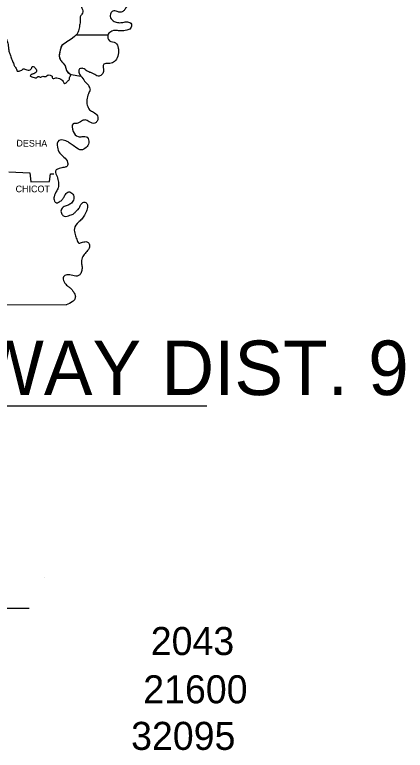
# Model space of a CAD drawing. Extents: x 309389.3 to 309420.2, y 336441.4 to 336461.2.
# Drawn here: x 309417.747 to 309420.196, y 336451.782 to 336456.398 of the extents above; entities that cross this region are included whole.
import ezdxf

# ---------------------------------------------------------------- set-up
doc = ezdxf.new("R2010")
doc.units = 0
doc.layers.add('Level 1', color=7, linetype='Continuous')
doc.layers.add('Level 63', color=7, linetype='Continuous')

msp = doc.modelspace()

# ---------------------------------------------------------------- linework, layer by layer
at = {"layer": 'Level 63'}
for p, q in [((309418.3313, 336456.2694), (309418.1305, 336456.2694)), ((309413.7435, 336453.9437), (309418.9521, 336453.9437)), ((309417.9364, 336452.8683), (309417.9364, 336452.8683)), ((309414.7103, 336452.6728), (309417.8386, 336452.6728))]:
    msp.add_line(p, q, dxfattribs=at)
for points in [[(309418.1289, 336456.2674), (309418.1221, 336456.2615), (309418.1016, 336456.2449), (309418.084, 336456.2352), (309418.0654, 336456.2215), (309418.0429, 336456.2048), (309418.0322, 336456.1765), (309418.0263, 336456.1374), (309418.0341, 336456.1139), (309418.0517, 336456.0934), (309418.0634, 336456.0768), (309418.0722, 336456.0475), (309418.0938, 336456.0269), (309418.1006, 336456.024), (309418.1622, 336456.0132)], [(309414.4855, 336455.3749), (309414.4874, 336454.584), (309418.0703, 336454.5781)], [(309417.7105, 336455.413), (309417.8415, 336455.4052), (309417.8474, 336455.3485), (309417.9657, 336455.3524), (309417.9706, 336455.4003), (309417.9931, 336455.4003)]]:
    msp.add_lwpolyline(points, dxfattribs=at)
for points in [[(309418.8934, 336457.2186), (309418.8709, 336457.1903), (309418.8377, 336457.2079), (309418.8377, 336457.2313), (309418.8426, 336457.2558), (309418.8309, 336457.2714), (309418.8103, 336457.2646), (309418.8103, 336457.2343), (309418.8084, 336457.2049), (309418.8025, 336457.1629), (309418.8162, 336457.1502), (309418.8475, 336457.1463), (309418.87, 336457.1404), (309418.8836, 336457.1179), (309418.8827, 336457.0905), (309418.8719, 336457.0642), (309418.8563, 336457.0426), (309418.8318, 336457.0348), (309418.8123, 336457.0475), (309418.8045, 336457.0729), (309418.7957, 336457.0954), (309418.779, 336457.1121), (309418.7614, 336457.0935), (309418.7575, 336457.0593), (309418.7585, 336457.0299), (309418.7585, 336456.9899), (309418.7839, 336456.9635), (309418.7996, 336456.9332), (309418.7947, 336456.9058), (309418.7761, 336456.8735), (309418.7683, 336456.8452), (309418.7605, 336456.807), (309418.7614, 336456.765), (309418.7546, 336456.7239), (309418.7409, 336456.6966), (309418.7155, 336456.6741), (309418.6989, 336456.6594), (309418.6852, 336456.6448), (309418.6784, 336456.6154), (309418.6735, 336456.5949), (309418.6549, 336456.5705), (309418.6402, 336456.5685), (309418.6285, 336456.5783), (309418.6246, 336456.5949), (309418.6246, 336456.6115), (309418.6168, 336456.6281), (309418.5923, 336456.635), (309418.5728, 336456.634), (309418.564, 336456.6203), (309418.5767, 336456.5822), (309418.5816, 336456.5578), (309418.5747, 336456.5245), (309418.5786, 336456.5206), (309418.5434, 336456.502), (309418.5151, 336456.4991), (309418.4916, 336456.4923), (309418.4691, 336456.4776), (309418.4584, 336456.4561), (309418.4428, 336456.4385), (309418.4291, 336456.4219), (309418.4105, 336456.4141), (309418.39, 336456.418), (309418.3626, 336456.4209), (309418.3469, 336456.4013), (309418.3518, 336456.373), (309418.3704, 336456.3564), (309418.3978, 336456.3486), (309418.4261, 336456.3505), (309418.4535, 336456.3534), (309418.4789, 336456.3398), (309418.474, 336456.3134), (309418.4496, 336456.3007), (309418.4134, 336456.2967), (309418.3841, 336456.2997), (309418.3489, 336456.2919), (309418.3313, 336456.2694), (309418.3411, 336456.2352), (309418.3792, 336456.2215), (309418.3968, 336456.1892), (309418.3978, 336456.1589), (309418.3851, 336456.1188), (309418.3675, 336456.1002), (309418.3333, 336456.0924), (309418.3069, 336456.0875), (309418.303, 336456.0426), (309418.2912, 336456.0201), (309418.2707, 336456.0132), (309418.2414, 336456.0279), (309418.2238, 336456.0347), (309418.2023, 336456.0445), (309418.1749, 336456.0611), (309418.1544, 336456.0582), (309418.1602, 336456.0152), (309418.1622, 336456.0132), (309418.1856, 336455.981), (309418.2091, 336455.9556), (309418.2199, 336455.9253)], [(309417.8806, 336456.9038), (309417.8836, 336456.8637), (309417.907, 336456.8579), (309417.9168, 336456.8471), (309417.9217, 336456.8246), (309417.9383, 336456.8149), (309417.9608, 336456.8012), (309417.9745, 336456.7914), (309417.9843, 336456.7758), (309417.9901, 336456.7503), (309418.0058, 336456.7337), (309418.0273, 336456.7259), (309418.0429, 336456.7073), (309418.0527, 336456.6809), (309418.0683, 336456.6692), (309418.084, 336456.6487), (309418.0918, 336456.6399), (309418.1055, 336456.6164), (309418.1192, 336456.6047), (309418.1289, 336456.5978), (309418.1446, 336456.593), (309418.1641, 336456.5802), (309418.1768, 336456.5607), (309418.1768, 336456.546), (309418.172, 336456.5235), (309418.168, 336456.5001), (309418.1661, 336456.4737), (309418.1641, 336456.4502), (309418.1729, 336456.4307), (309418.168, 336456.4013), (309418.1583, 336456.3857), (309418.1573, 336456.3642), (309418.1544, 336456.3319), (309418.1505, 336456.3134), (309418.1417, 336456.2831), (309418.1289, 336456.2674)], [(309417.5092, 336456.3984), (309417.5238, 336456.3886), (309417.5443, 336456.3896), (309417.558, 336456.3955), (309417.5688, 336456.3945), (309417.5835, 336456.3857), (309417.5932, 336456.374), (309417.6001, 336456.3652), (309417.605, 336456.3515), (309417.605, 336456.3388), (309417.6098, 336456.3212), (309417.6157, 336456.3143), (309417.6235, 336456.3016), (309417.6284, 336456.2899), (309417.6314, 336456.2821), (309417.6421, 336456.2694), (309417.6519, 336456.2703), (309417.6607, 336456.2694), (309417.6724, 336456.2625), (309417.69, 336456.2488), (309417.6929, 336456.2449), (309417.7047, 336456.2195), (309417.7066, 336456.2039), (309417.7086, 336456.1833), (309417.7125, 336456.1638), (309417.7203, 336456.1423), (309417.7242, 336456.1276), (309417.733, 336456.1071), (309417.7389, 336456.0934), (309417.7467, 336456.0758), (309417.7584, 336456.0563), (309417.7633, 336456.0445), (309417.7799, 336456.0455), (309417.7917, 336456.0504), (309417.8005, 336456.0582), (309417.8112, 336456.0572), (309417.823, 336456.0533), (309417.8386, 336456.0504), (309417.8484, 336456.0563), (309417.8533, 336456.0602), (309417.8542, 336456.069), (309417.863, 336456.0739), (309417.8728, 336456.067), (309417.8836, 336456.0514), (309417.8836, 336456.0416), (309417.8797, 336456.0357), (309417.867, 336456.0279), (309417.8494, 336456.022), (309417.8445, 336456.0152), (309417.8611, 336456.0074), (309417.8875, 336456.0054), (309417.8943, 336456.0113), (309417.9119, 336456.0064), (309417.9188, 336456.0113), (309417.9422, 336456.0103), (309417.953, 336456.0181), (309417.9745, 336456.0172), (309417.9813, 336456.0123), (309417.9813, 336456.0035), (309417.9989, 336455.9996), (309418.0116, 336456.0025), (309418.0283, 336455.9976), (309418.0429, 336455.9898), (309418.0507, 336455.979), (309418.0605, 336455.9673), (309418.0693, 336455.9702), (309418.0762, 336455.979), (309418.0908, 336455.9947), (309418.0908, 336456.0044), (309418.0947, 336456.0113), (309418.0996, 336456.0211)], [(309418.1221, 336456.2615), (309418.1016, 336456.2449), (309418.084, 336456.2352), (309418.0654, 336456.2215), (309418.0429, 336456.2048), (309418.0322, 336456.1765), (309418.0263, 336456.1374), (309418.0341, 336456.1139), (309418.0517, 336456.0934), (309418.0634, 336456.0768), (309418.0722, 336456.0475), (309418.0938, 336456.0269), (309418.1006, 336456.024)], [(309418.2199, 336455.9253), (309418.2101, 336455.9028), (309418.1993, 336455.8637), (309418.2023, 336455.8304), (309418.2169, 336455.8021), (309418.2404, 336455.7864), (309418.2658, 336455.764), (309418.2639, 336455.7297), (309418.2492, 336455.717), (309418.215, 336455.7258), (309418.1886, 336455.7376), (309418.1661, 336455.7307), (309418.1358, 336455.7161), (309418.1133, 336455.7131), (309418.1143, 336455.6662), (309418.1446, 336455.633), (309418.171, 336455.633), (309418.2013, 336455.629), (309418.212, 336455.5939), (309418.1944, 336455.5645), (309418.1651, 336455.5499), (309418.128, 336455.5675), (309418.1016, 336455.586), (309418.0752, 336455.6036), (309418.0419, 336455.6124), (309418.0234, 336455.6085), (309418.0146, 336455.5675), (309418.0302, 336455.5303), (309418.0556, 336455.5049), (309418.0791, 336455.4717), (309418.0752, 336455.4472), (309418.0576, 336455.4404), (309418.0263, 336455.4335), (309418.0077, 336455.4238), (309418.0028, 336455.4159), (309418.0126, 336455.3827), (309418.0214, 336455.3465), (309418.0214, 336455.3192), (309418.0107, 336455.2937), (309417.994, 336455.2546), (309417.996, 336455.2292), (309418.0077, 336455.2175), (309418.0224, 336455.2214), (309418.0419, 336455.2351), (309418.0546, 336455.2507), (309418.0654, 336455.2703), (309418.0859, 336455.2869), (309418.1113, 336455.2722), (309418.1172, 336455.2419), (309418.1026, 336455.2155), (309418.082, 336455.2038), (309418.0566, 336455.194), (309418.038, 336455.1725), (309418.0429, 336455.1471), (309418.0576, 336455.1334), (309418.0938, 336455.1403), (309418.1182, 336455.151), (309418.1319, 336455.1647), (309418.1485, 336455.1813), (309418.1573, 336455.1979), (309418.17, 336455.2155), (309418.1925, 336455.2204), (309418.2032, 336455.2058), (309418.1993, 336455.1725), (309418.1856, 336455.1412), (309418.1671, 336455.1148), (309418.1465, 336455.0963), (309418.1211, 336455.0562), (309418.126, 336455.019), (309418.1358, 336454.9887), (309418.1495, 336454.9653), (309418.1729, 336454.9702), (309418.1993, 336454.9731), (309418.215, 336454.9604), (309418.213, 336454.933), (309418.1935, 336454.9066), (309418.1749, 336454.8812), (309418.1651, 336454.846), (309418.169, 336454.8216), (309418.169, 336454.7991), (309418.1612, 336454.7746), (309418.1475, 336454.7609), (309418.1113, 336454.7619), (309418.0732, 336454.7658), (309418.0527, 336454.7541), (309418.0566, 336454.7209), (309418.0791, 336454.6964), (309418.0947, 336454.6837), (309418.1172, 336454.6563), (309418.127, 336454.6339), (309418.1241, 336454.6143), (309418.1104, 336454.5977), (309418.0703, 336454.5781)]]:
    msp.add_spline(points, degree=3, dxfattribs=at)

# ---------------------------------------------------------------- texts
at = {"layer": 'Level 1'}
for s, height, p in [('ARKANSAS HIGHWAY DIST. 9', 0.342154, (309413.7351, 336454.0111)), ('2043', 0.17597, (309418.6002, 336452.3795)), ('21600', 0.17597, (309418.5531, 336452.0765)), ('32095', 0.17597, (309418.4769, 336451.7842))]:
    msp.add_text(s, height=height, dxfattribs=at).set_placement(p)
at = {"layer": 'Level 63'}
msp.add_text('DESHA', height=0.04203, rotation=359.3704, dxfattribs=at).set_placement((309417.7575, 336455.5714))
msp.add_text('CHICOT', height=0.04204, dxfattribs=at).set_placement((309417.7526, 336455.284))

doc.saveas('drawing.dxf')
